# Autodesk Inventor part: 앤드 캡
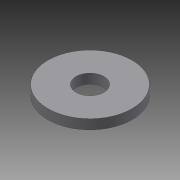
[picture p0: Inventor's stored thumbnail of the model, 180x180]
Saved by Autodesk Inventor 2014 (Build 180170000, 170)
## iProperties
Created: 2024-02
Part Number: 앤드 캡
Material: 강철, 연강
Document SubType Name: Modeling
Designer: mdu-01
Density: 7.86 g/cm^3
Mass: 5.06089 g
Surface Area: 7.52097 cm^2
Volume: 0.643879 cm^3
Appearance: 기본값(1)
Author: mdu-01
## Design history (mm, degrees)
sketch "스케치1"
  geometry: L1 (-0.3, -2.5)-(-0.3, 2.5) reference; C1 r 10 at (8.5, 0); C2 r 3.3 at (8.5, 0); A1 r 6.5 centre (8.5, 0) between (2.5, -2.5) and (2.5, 2.5) reference; 1 further point
  constraints: 2 centre point, 2 coincident
  dimensions: "d0" = 20 diameter of C1; "d1" = 6.6 diameter of C2
extrude "돌출1" new body sketch "스케치1" distance "d2" = 2.3; taper "d3" = 0 deg
node "솔리드1"
node "참조1"
node "참조2"
